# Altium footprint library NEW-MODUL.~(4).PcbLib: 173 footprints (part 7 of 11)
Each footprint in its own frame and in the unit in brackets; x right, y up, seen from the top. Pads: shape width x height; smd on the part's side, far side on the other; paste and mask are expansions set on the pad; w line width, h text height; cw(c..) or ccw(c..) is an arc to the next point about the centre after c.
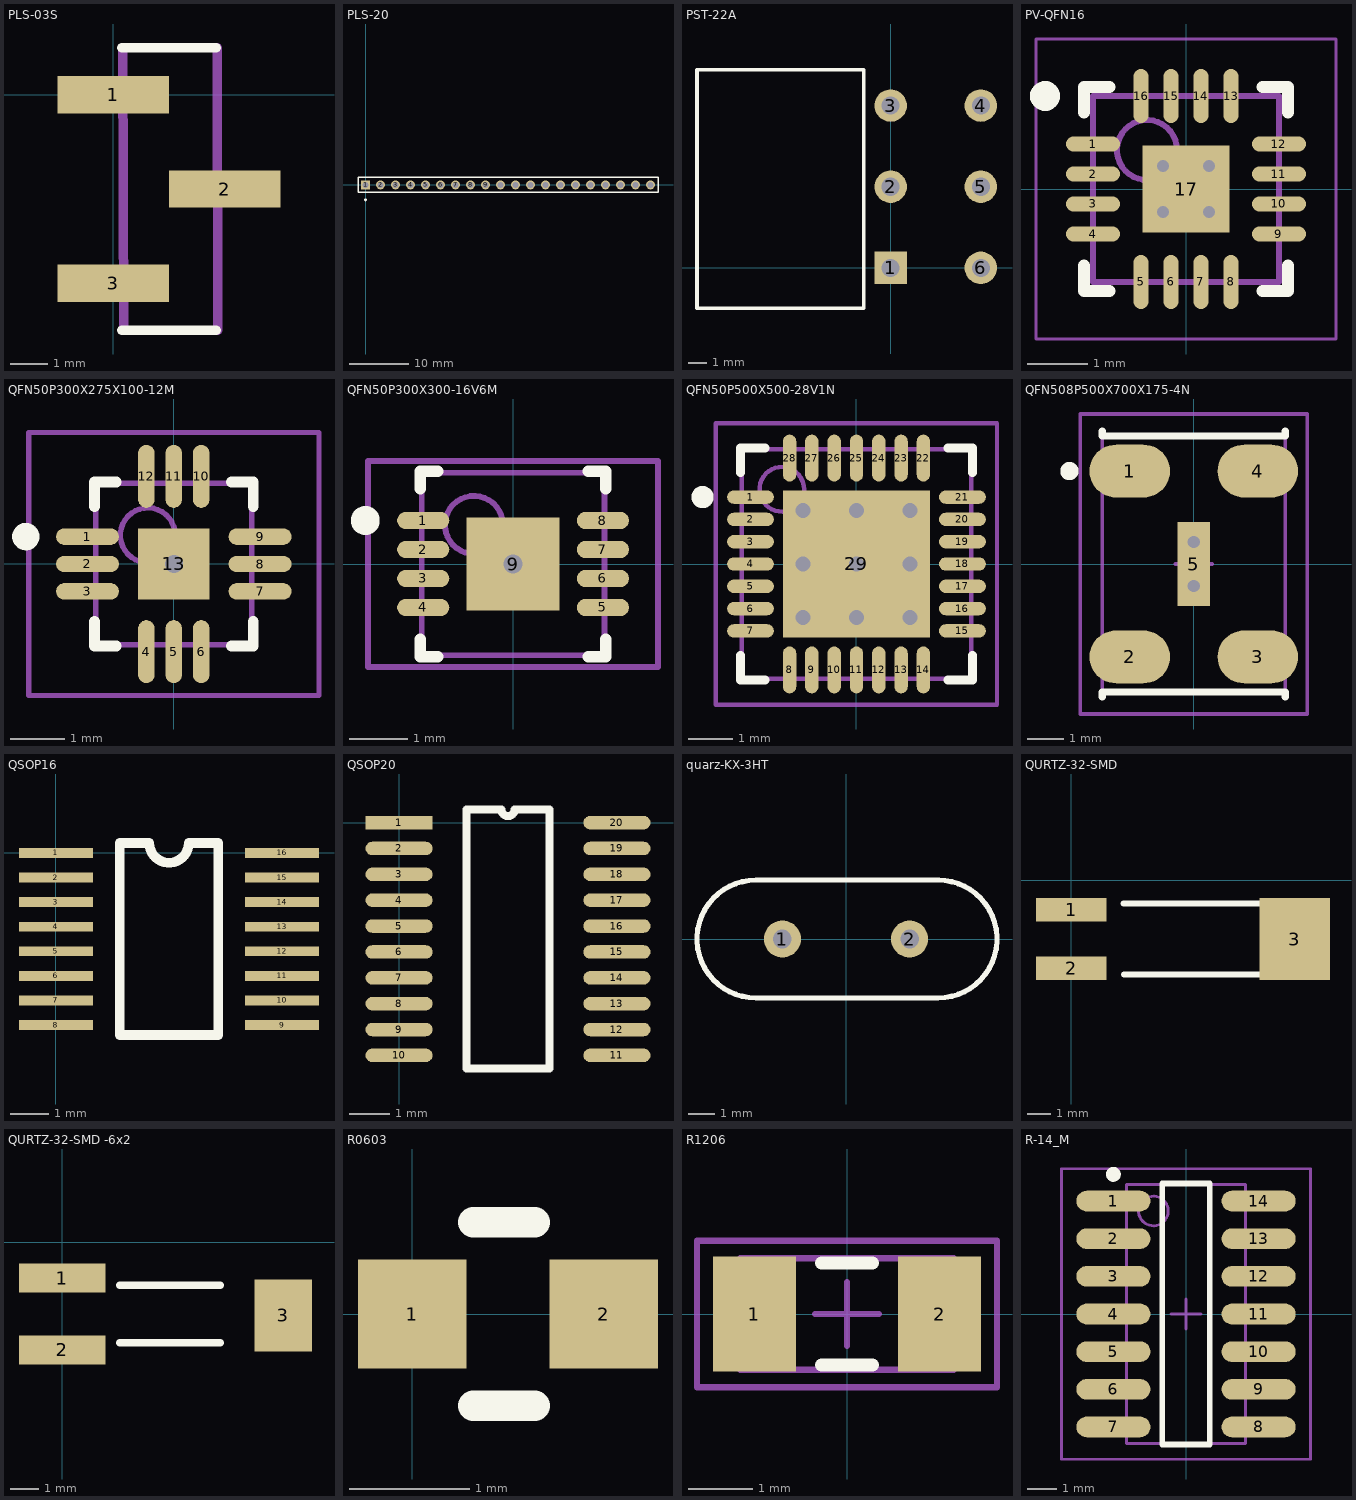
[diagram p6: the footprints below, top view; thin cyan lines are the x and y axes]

## PLS-03S [mm]
pads (3):
  rect 3x1 smd: 1(0,0) 2(3,-2.54) 3(0,-5.08)
Top Overlay:
  lines w0.254: 0.23,-6.35 2.77,-6.35 ; 0.23,1.27 2.77,1.27
Mechanical 1:
  lines w0.254: 0.254,1.27 0.278,-6.35 ; 2.794,1.27 2.818,-6.35
3D body "pin_header_a-sl254-eg-g03mp1.stp": height 9.86, standoff 0.02, extent -0.976,-6.35 4.024,1.27

## PLS-20 [mm] "Connector; , Low Profile Male Header, Thru-Hole; 20 Position; Vertical; Pitch 2.54 mm"
height 9.45
pads (20):
  rect 1.5x1.5 hole 1 paste-2539.97 mask+0.102: 1(0,0)
  round 1.5 hole 1 paste-2539.97 mask+0.102: 2(2.54,0) 3(5.08,0) 4(7.62,0) 5(10.16,0) 6(12.7,0) 7(15.24,0) 8(17.78,0) 9(20.32,0) 10(22.86,0) 11(25.4,0) 12(27.94,0) 13(30.48,0) 14(33.02,0) 15(35.56,0) 16(38.1,0) 17(40.64,0) 18(43.18,0) 19(45.72,0) 20(48.26,0)
Top Overlay:
  circle w0.25: c0,-2.54 r0.125
  lines w0.254: -1.27,-1.27 -1.27,1.27 49.53,1.27 49.53,-1.27 -1.27,-1.27
3D body "User Library-PLS-1.step": height 8.44, standoff -3, extent 31.75,-1.27 34.29,1.27
3D body "User Library-PLS-1.step": height 8.44, standoff -3, extent 34.29,-1.27 36.83,1.27
3D body "User Library-PLS-1.step": height 8.44, standoff -3, extent -1.27,-1.27 1.27,1.27
3D body "User Library-PLS-1.step": height 8.44, standoff -3, extent 1.27,-1.27 3.81,1.27
3D body "User Library-PLS-1.step": height 8.44, standoff -3, extent 3.81,-1.27 6.35,1.27
3D body "User Library-PLS-1.step": height 8.44, standoff -3, extent 6.35,-1.27 8.89,1.27
3D body "User Library-PLS-1.step": height 8.44, standoff -3, extent 8.89,-1.27 11.43,1.27
3D body "User Library-PLS-1.step": height 8.44, standoff -3, extent 36.83,-1.27 39.37,1.27
3D body "User Library-PLS-1.step": height 8.44, standoff -3, extent 11.43,-1.27 13.97,1.27
3D body "User Library-PLS-1.step": height 8.44, standoff -3, extent 39.37,-1.27 41.91,1.27
3D body "User Library-PLS-1.step": height 8.44, standoff -3, extent 13.97,-1.27 16.51,1.27
3D body "User Library-PLS-1.step": height 8.44, standoff -3, extent 41.91,-1.27 44.45,1.27
3D body "User Library-PLS-1.step": height 8.44, standoff -3, extent 16.51,-1.27 19.05,1.27
3D body "User Library-PLS-1.step": height 8.44, standoff -3, extent 44.45,-1.27 46.99,1.27
3D body "User Library-PLS-1.step": height 8.44, standoff -3, extent 19.05,-1.27 21.59,1.27
3D body "User Library-PLS-1.step": height 8.44, standoff -3, extent 46.99,-1.27 49.53,1.27
3D body "User Library-PLS-1.step": height 8.44, standoff -3, extent 21.59,-1.27 24.13,1.27
3D body "User Library-PLS-1.step": height 8.44, standoff -3, extent 24.13,-1.27 26.67,1.27
3D body "User Library-PLS-1.step": height 8.44, standoff -3, extent 26.67,-1.27 29.21,1.27
3D body "User Library-PLS-1.step": height 8.44, standoff -3, extent 29.21,-1.27 31.75,1.27

## PST-22A [mm]
pads (6):
  rect 1.8x1.8 hole 1: 1(0,0)
  round 1.8 hole 1: 2(0,4.5) 3(0,9) 4(5,9) 5(5,4.5) 6(5,0)
Top Overlay:
  lines w0.2: -10.75,-2.25 -10.75,11 -1.5,11 -1.5,-2.25 -10.75,-2.25
3D body "SW3dPS-SWITCH SPDT_O_N_O.STEP": height 9.37, standoff -2.49, extent -30.107,-2.1 0.925,10.6

## PV-QFN16 [mm] "QFN, 16-Leads, Body 3x3mm, Pitch 0.5mm, Thermal Pad 1.75x1.75mm, IPC Low Density"
height 0.8
pads (17):
  oval 0.9x0.25 smd: 1(-1.55,0.75) 2(-1.55,0.25) 3(-1.55,-0.25) 4(-1.55,-0.75) 9(1.55,-0.75) 10(1.55,-0.25) 11(1.55,0.25) 12(1.55,0.75)
  oval 0.25x0.9 smd: 5(-0.75,-1.55) 6(-0.25,-1.55) 7(0.25,-1.55) 8(0.75,-1.55) 13(0.75,1.55) 14(0.25,1.55) 15(-0.25,1.55) 16(-0.75,1.55)
  rect 1.45x1.45 smd: 17(0,0)
via -0.381,-0.381 diameter 0.5 hole 0.2
via 0.381,-0.381 diameter 0.5 hole 0.2
via 0.381,0.381 diameter 0.5 hole 0.2
via -0.381,0.381 diameter 0.5 hole 0.2
Top Overlay:
  circle w0.25: c-2.35,1.55 r0.125
  lines w0.2: -1.7,-1.275 -1.7,-1.7 -1.275,-1.7 ; -1.7,1.275 -1.7,1.7 -1.275,1.7 ; 1.275,-1.7 1.7,-1.7 1.7,-1.275 ; 1.275,1.7 1.7,1.7 1.7,1.275
Mechanical 13:
  circle w0.1: c-0.65,0.65 r0.5
  lines w0.1: -1.55,-1.55 -1.55,1.55 1.55,1.55 1.55,-1.55 -1.55,-1.55
Mechanical 15:
  lines w0.05: -2.5,-2.5 -2.5,2.5 2.5,2.5 2.5,-2.5 -2.5,-2.5
  lines w0.1: -0.5,0 0.5,0 ; 0,-0.5 0,0.5
3D body "User Library-QFN-16.step": height 0.9, standoff 0, extent -1.501,-1.501 1.501,1.501

## QFN50P300X275X100-12M [mm] "QFN, 12-Leads, Body 3,0x2,8mm (max), Pitch 0,50mm, IPC Low Density"
height 1
pads (13):
  oval 1.15x0.3 smd: 1(-1.575,0.5) 2(-1.575,0) 3(-1.575,-0.5) 7(1.575,-0.5) 8(1.575,0) 9(1.575,0.5)
  oval 0.3x1.15 smd: 4(-0.5,-1.6) 5(0,-1.6) 6(0.5,-1.6) 10(0.5,1.6) 11(0,1.6) 12(-0.5,1.6)
  rect 1.3x1.3 smd: 13(0,0)
via 0,0 diameter 0.66 hole 0.33
Top Overlay:
  circle w0.25: c-2.7,0.5 r0.125
  lines w0.2: -1.45,-1.05 -1.45,-1.5 -1.05,-1.5 ; -1.45,1.05 -1.45,1.5 -1.05,1.5 ; 1.05,-1.5 1.45,-1.5 1.45,-1.05 ; 1.05,1.5 1.45,1.5 1.45,1.05
Mechanical 13:
  circle w0.1: c-0.475,0.525 r0.5
  lines w0.1: -1.425,-1.475 -1.425,1.475 1.425,1.475 1.425,-1.475 -1.425,-1.475
Mechanical 15:
  lines w0.1: -0.5,0 0.5,0 ; 0,-0.5 0,0.5 ; -2.65,-2.4 -2.65,2.4 2.65,2.4 2.65,-2.4 -2.65,-2.4
3D body "User Library-LFCSP.STEP": height 0.85, standoff 0, extent -1.525,-1.525 1.525,1.525

## QFN50P300X300-16V6M [mm] "QFN, 16-Leads, Body 3x3mm, Pitch 0.5mm, IPC Low Density"
height 1
pads (9):
  oval 0.9x0.3 smd: 1(-1.55,0.75) 2(-1.55,0.25) 3(-1.55,-0.25) 4(-1.55,-0.75) 5(1.55,-0.75) 6(1.55,-0.25) 7(1.55,0.25) 8(1.55,0.75)
  rect 1.6x1.6 smd: 9(0,0)
via 0,0 diameter 0.66 hole 0.33
Top Overlay:
  circle w0.25: c-2.55,0.75 r0.125
  lines w0.2: -1.6,-1.3 -1.6,-1.6 -1.3,-1.6 ; -1.6,1.3 -1.6,1.6 -1.3,1.6 ; 1.3,-1.6 1.6,-1.6 1.6,-1.3 ; 1.3,1.6 1.6,1.6 1.6,1.3
Mechanical 13:
  circle w0.1: c-0.675,0.675 r0.5
  lines w0.1: -1.575,-1.575 1.575,-1.575 1.575,1.575 -1.575,1.575 -1.575,-1.575
Mechanical 15:
  lines w0.1: -0.5,0 0.5,0 ; 0,-0.5 0,0.5 ; -2.5,-1.778 2.5,-1.778 2.5,1.778 -2.5,1.778 -2.5,-1.778

## QFN50P500X500-28V1N [mm] "QFN, 28-Leads, Body 5x5mm, Pitch 0.5mm, IPC Medium Density"
height 1
pads (29):
  oval 1.05x0.3 smd: 1(-2.375,1.5) 2(-2.375,1) 3(-2.375,0.5) 4(-2.375,0) 5(-2.375,-0.5) 6(-2.375,-1) 7(-2.375,-1.5) 15(2.375,-1.5) 16(2.375,-1) 17(2.375,-0.5) 18(2.375,0) 19(2.375,0.5) 20(2.375,1) 21(2.375,1.5)
  oval 0.3x1.05 smd: 8(-1.5,-2.375) 9(-1,-2.375) 10(-0.5,-2.375) 11(0,-2.375) 12(0.5,-2.375) 13(1,-2.375) 14(1.5,-2.375) 22(1.5,2.375) 23(1,2.375) 24(0.5,2.375) 25(0,2.375) 26(-0.5,2.375) 27(-1,2.375) 28(-1.5,2.375)
  rect 3.3x3.3 smd: 29(0,0)
via -1.2,1.2 diameter 0.66 hole 0.33
via 0,1.2 diameter 0.66 hole 0.33
via 1.2,1.2 diameter 0.66 hole 0.33
via -1.2,0 diameter 0.66 hole 0.33
via 0,0 diameter 0.66 hole 0.33
via 1.2,0 diameter 0.66 hole 0.33
via -1.2,-1.2 diameter 0.66 hole 0.33
via 0,-1.2 diameter 0.66 hole 0.33
via 1.2,-1.2 diameter 0.66 hole 0.33
Top Overlay:
  circle w0.25: c-3.45,1.5 r0.125
  lines w0.2: -2.6,-2.05 -2.6,-2.6 -2.05,-2.6 ; -2.6,2.05 -2.6,2.6 -2.05,2.6 ; 2.05,-2.6 2.6,-2.6 2.6,-2.05 ; 2.05,2.6 2.6,2.6 2.6,2.05
Mechanical 13:
  circle w0.1: c-1.675,1.675 r0.5
  lines w0.1: -2.575,-2.575 -2.575,2.575 2.575,2.575 2.575,-2.575 -2.575,-2.575
Mechanical 15:
  lines w0.1: -0.5,0 0.5,0 ; 0,-0.5 0,0.5 ; -3.15,-3.15 -3.15,3.15 3.15,3.15 3.15,-3.15 -3.15,-3.15
3D body "User Library-CP2201_QFN28.step": height 1.07, standoff 0, extent -2.528,-2.498 2.472,2.502

## QFN508P500X700X175-4N [mm] "QFN, 4-Leads, Body 7,0x5,0mm (max), Pitch 5,08mm, IPC Medium Density"
height 1.75
pads (5):
  oval 2.2x1.45 smd: 1(-1.75,2.54) 2(-1.75,-2.54) 3(1.75,-2.54) 4(1.75,2.54)
  rect 0.9x2.3 smd: 5(0,0)
via 0,-0.6 diameter 0.66 hole 0.33
via 0,0.6 diameter 0.66 hole 0.33
Top Overlay:
  circle w0.25: c-3.4,2.54 r0.125
  lines w0.2: -2.5,-3.625 -2.5,-3.5 1.375,-3.5 ; -2.5,3.625 -2.5,3.5 1.375,3.5 ; -1.375,-3.5 2.5,-3.5 2.5,-3.625 ; -1.375,3.5 2.5,3.5 2.5,3.625
Mechanical 13:
  circle w0.1: c-1.55,2.55 r0.5
  lines w0.1: -2.5,-3.5 2.5,-3.5 2.5,3.5 -2.5,3.5 -2.5,-3.5
Mechanical 15:
  lines w0.1: -0.5,0 0.5,0 ; 0,-0.5 0,0.5 ; -3.1,-4.1 3.1,-4.1 3.1,4.1 -3.1,4.1 -3.1,-4.1
3D body: height 1.75, standoff 0.01, extent -2.5,-3.5 2.5,3.5

## QSOP16 [mil]
pads (16):
  rect 75x10 smd: 1(0,0) 2(0,-25) 3(0,-50) 4(0,-75) 5(0,-100) 6(0,-125) 7(0,-150) 8(0,-175) 9(230,-175) 10(230,-150) 11(230,-125) 12(230,-100) 13(230,-75) 14(230,-50) 15(230,-25) 16(230,0)
Top Overlay:
  lines w10: 65,-185 65,10 95,10 ccw(c115,10) 135,10 165,10 165,-185 65,-185
3D body "User Library-MAX_QSOP16.step": height 69.72, standoff 0, extent -2.5,-186.03 234.51,10.03

## QSOP20 [mm]
pads (20):
  rect 1.65x0.33 smd: 1(0,0)
  oval 1.65x0.33 smd: 2(0,-0.635) 3(0,-1.27) 4(0,-1.905) 5(0,-2.54) 6(0,-3.175) 7(0,-3.81) 8(0,-4.445) 9(0,-5.08) 10(0,-5.715) 11(5.35,-5.715) 12(5.35,-5.08) 13(5.35,-4.445) 14(5.35,-3.81) 15(5.35,-3.175) 16(5.35,-2.54) 17(5.35,-1.905) 18(5.35,-1.27) 19(5.35,-0.635) 20(5.35,0)
Top Overlay:
  lines w0.2: 1.66,-6.032 3.69,-6.032 3.69,0.318 2.834,0.318 cw(c2.675,0.318) 2.516,0.318 1.66,0.318 1.66,-6.032
3D body "User Library-IPC SO.step": height 1.75, standoff 0, extent -0.328,-7.24 5.728,1.5

## quarz-KX-3HT [mm]
pads (2):
  round 1.4 hole 0.7: 1(-2.4,0) 2(2.4,0)
Top Overlay:
  lines w0.2: 3.45,-2.225 -3.4,-2.225 cw(c-3.4,0) -3.4,2.225 3.5,2.225 ; 3.475,-2.225 ccw(c3.475,0) 3.475,2.225
3D body "hs49s.step": height 3.5, standoff -4, extent -5.675,-2.325 5.675,2.325

## QURTZ-32-SMD [mm]
pads (3):
  rect 3x1 smd: 1(0,-1.25) 2(0,-3.75)
  rect 3x3.5 smd: 3(9.5,-2.5)
Top Overlay:
  lines w0.254: 2.21,-1 10.25,-1 ; 2.25,-4 10.25,-4
3D body "User Library-AB26TRB.step": height 2, standoff 0, extent -0.75,-3.9 8.25,-1.1

## QURTZ-32-SMD -6x2 [mm]
pads (3):
  rect 3x1 smd: 1(0,-1.25) 2(0,-3.75)
  rect 2x2.5 smd: 3(7.675,-2.55)
Top Overlay:
  lines w0.254: 2,-3.5 5.5,-3.5 ; 2,-1.5 5.5,-1.5
3D body "User Library-AB26TRB.step": height 2, standoff 0, extent -0.75,-3.9 8.25,-1.1

## R0603 [mm]
pads (2):
  rect 0.9x0.9 smd: 1(0,0) 2(1.587,0)
Top Overlay:
  lines w0.254: 0.508,-0.762 1.016,-0.762 ; 0.508,0.762 1.016,0.762
3D body "User Library-0603 SMD Capacitor.step": height 0.3, standoff 0, extent -0.038,-0.4 1.562,0.4

## R1206 [mm] "R1206"
pads (2):
  rect 1.3x1.8 smd: 1(-1.45,0) 2(1.45,0)
Top Overlay:
  lines w0.2: -0.4,-0.8 0.4,-0.8 ; -0.4,0.8 0.4,0.8
Mechanical 13:
  lines w0.1: -1.675,-0.875 1.675,-0.875 1.675,0.875 -1.675,0.875 -1.675,-0.875
Mechanical 15:
  lines w0.1: -0.5,0 0.5,0 ; 0,-0.5 0,0.5 ; -2.35,-1.15 2.35,-1.15 2.35,1.15 -2.35,1.15 -2.35,-1.15
3D body "User Library-RESC3216X06N.step": height 0.55, standoff 0, extent -1.6,-0.8 1.6,0.8

## R-14_M [mm] "14-Pin Narrow Body Small Outline Integrated Circuit 1.27 mm Pitch, IPC Low Density"
height 1.75
pads (14):
  oval 2.5x0.7 smd: 1(-2.45,3.81) 2(-2.45,2.54) 3(-2.45,1.27) 4(-2.45,0) 5(-2.45,-1.27) 6(-2.45,-2.54) 7(-2.45,-3.81) 8(2.45,-3.81) 9(2.45,-2.54) 10(2.45,-1.27) 11(2.45,0) 12(2.45,1.27) 13(2.45,2.54) 14(2.45,3.81)
Top Overlay:
  circle w0.25: c-2.45,4.71 r0.125
  lines w0.2: -0.8,-4.4 -0.8,4.4 0.8,4.4 0.8,-4.4 -0.8,-4.4
Mechanical 13:
  circle w0.1: c-1.1,3.475 r0.5
  lines w0.1: -2,-4.375 -2,4.375 2,4.375 2,-4.375 -2,-4.375
Mechanical 15:
  lines w0.1: -0.5,0 0.5,0 ; 0,-0.5 0,0.5 ; -4.2,-4.9 -4.2,4.9 4.2,4.9 4.2,-4.9 -4.2,-4.9
3D body "User Library-SOIC-14.step": height 1.75, standoff 0, extent -3,-4.375 3,4.375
